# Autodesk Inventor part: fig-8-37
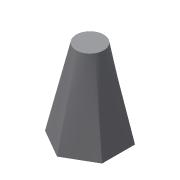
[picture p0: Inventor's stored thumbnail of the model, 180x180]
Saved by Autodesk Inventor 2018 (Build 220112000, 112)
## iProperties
Created: 2007-05
Part Number: fig-8-37
Document SubType Name: Modeling
Designer: Administrator
Density: 1 g/cm^3
Material: Generic
Appearance: Default
Author: Administrator
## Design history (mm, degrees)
sketch "Sketch1"
  geometry: L1 (0, 30)-(25.981, 15); L2 (25.981, 15)-(25.981, -15); L3 (25.981, -15)-(0, -30); L4 (0, -30)-(-25.981, -15); L5 (-25.981, -15)-(-25.981, 15); L6 (-25.981, 15)-(0, 30); 2 further points
  constraints: 12 end point, 1 coincident, 1 vertical, 14 other
workplane "Work Plane1"
sketch "Sketch2"
  geometry: C1 r 12.5 at (0, 0)
  constraints: 1 centre point, 1 other
sketch "Sketch3"
  geometry: L1 (0, 0)-(0, 75)
  constraints: 2 end point, 1 vertical, 1 other
loft "Loft1" dims "d5" = 0, "d6" = 90 deg, "d7" = 0, "d8" = 90 deg
body "Solid1"
other parameters: "d1" = 75
